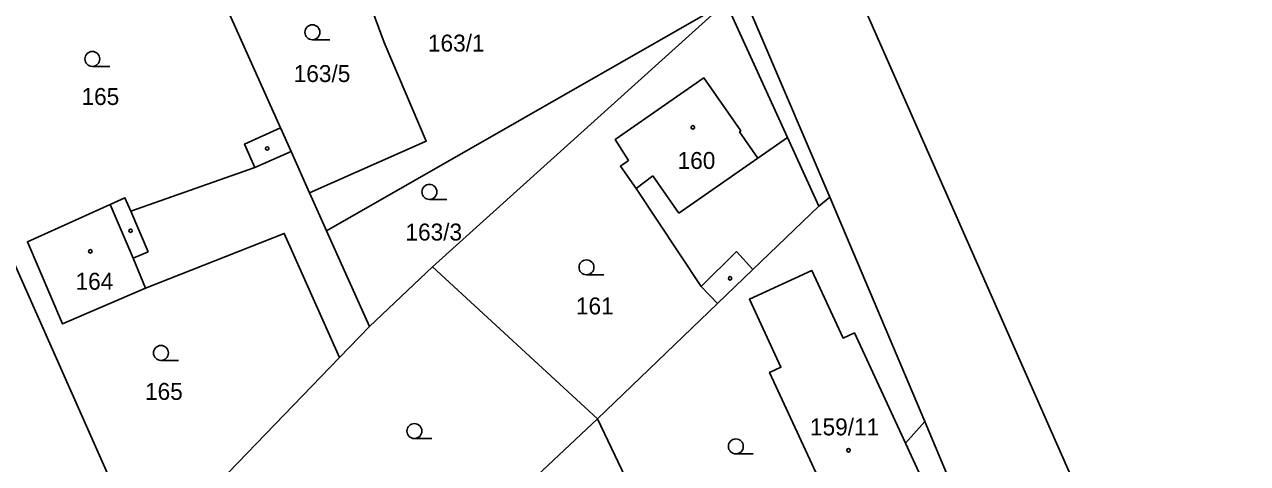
# Model space of a CAD drawing. Extents: x -724107 to -720612, y -1045267 to -1038441.
# Drawn here: x -722946.8 to -722824, y -1042363.1 to -1042319 of the extents above; entities that cross this region are included whole.
import ezdxf

# ---------------------------------------------------------------- set-up
doc = ezdxf.new("R2010")
doc.units = 0
for name, color, linetype in [('Hranice parcel', 7, 'Continuous'), ('Parcelní čísla', 7, 'Continuous'), ('Vnitřní kresba', 7, 'Continuous'), ('Značky budov', 7, 'Continuous'), ('Značky kultur', 7, 'Continuous')]:
    doc.layers.add(name, color=color, linetype=linetype)

msp = doc.modelspace()

# ---------------------------------------------------------------- linework, layer by layer
at = {"layer": 'Hranice parcel'}
for p, q in [((-722875.11, -1042288.78), (-722824.01, -1042404.46)), ((-722926.79, -1042316.73), (-722921.11, -1042329.42)), ((-722876.41, -1042316.85), (-722905.85, -1042343.37)), ((-722870.21, -1042330.38), (-722876.41, -1042316.85)), ((-722867.05, -1042337.26), (-722870.21, -1042330.38)), ((-722865.95, -1042336.37), (-722867.05, -1042337.26)), ((-722856.42, -1042358.89), (-722865.95, -1042336.37)), ((-722916.48, -1042339.75), (-722912.18, -1042349.36)), ((-722905.85, -1042343.37), (-722912.18, -1042349.36)), ((-722889.27, -1042358.62), (-722905.85, -1042343.37)), ((-722877.22, -1042347.03), (-722889.27, -1042358.62)), ((-722912.18, -1042349.36), (-722915.19, -1042352.47)), ((-722915.19, -1042352.47), (-722934.71, -1042372.64)), ((-722925.82, -1042392.75), (-722889.27, -1042358.62)), ((-722889.27, -1042358.62), (-722881.59, -1042374.72)), ((-722858.37, -1042361.05), (-722856.42, -1042358.89)), ((-722852.81, -1042367.41), (-722856.42, -1042358.89))]:
    msp.add_line(p, q, dxfattribs=at)
for points in [[(-722865.95, -1042336.37), (-722887.25, -1042286.6), (-722912.87, -1042230.53)], [(-722913.56, -1042312.92), (-722914, -1042313.18), (-722912.66, -1042316.01), (-722912.52, -1042315.95), (-722910.72, -1042320.84), (-722906.48, -1042330.75), (-722918.2, -1042335.92)], [(-722959.26, -1042316.99), (-722948.46, -1042341.61), (-722934.71, -1042372.64)], [(-722916.48, -1042339.75), (-722876.8, -1042317.07), (-722876.41, -1042316.85)], [(-722870.21, -1042330.38), (-722873.19, -1042332.46), (-722875.04, -1042329.82), (-722874.9, -1042329.73), (-722878.6, -1042324.41), (-722887.5, -1042330.6), (-722886.18, -1042332.69), (-722886.98, -1042333.25), (-722885.4, -1042335.51), (-722878.88, -1042345.33), (-722877.22, -1042347.03)], [(-722921.11, -1042329.42), (-722924.73, -1042331.04), (-722923.68, -1042333.4), (-722936.16, -1042337.78), (-722936.74, -1042336.43), (-722938.23, -1042337.1), (-722946.53, -1042340.84), (-722942.99, -1042349.09), (-722934.66, -1042345.49), (-722920.74, -1042340.01), (-722915.19, -1042352.47)], [(-722921.11, -1042329.42), (-722920.05, -1042331.78), (-722918.2, -1042335.92)], [(-722918.2, -1042335.92), (-722917.02, -1042338.54), (-722916.48, -1042339.75)], [(-722867.05, -1042337.26), (-722873.7, -1042343.64), (-722877.22, -1042347.03)], [(-722867.6, -1042371.3), (-722870.56, -1042369.01), (-722867.11, -1042364.49), (-722872, -1042353.96), (-722870.86, -1042353.43), (-722874.03, -1042346.62), (-722867.76, -1042343.73), (-722864.6, -1042350.51), (-722863.49, -1042349.99), (-722858.37, -1042361.05)], [(-722858.37, -1042361.05), (-722856.21, -1042365.7), (-722863.13, -1042374.77), (-722867.6, -1042371.3)]]:
    msp.add_lwpolyline(points, dxfattribs=at)
at = {"layer": 'Vnitřní kresba'}
for p, q in [((-722920.05, -1042331.78), (-722923.68, -1042333.4)), ((-722881.11, -1042337.99), (-722873.19, -1042332.46)), ((-722885.4, -1042335.51), (-722883.73, -1042334.23)), ((-722883.73, -1042334.23), (-722881.11, -1042337.99)), ((-722938.23, -1042337.1), (-722935.92, -1042342.49)), ((-722936.16, -1042337.78), (-722934.42, -1042341.84)), ((-722934.42, -1042341.84), (-722935.92, -1042342.49)), ((-722875.32, -1042341.81), (-722878.88, -1042345.33)), ((-722873.7, -1042343.64), (-722875.32, -1042341.81)), ((-722935.92, -1042342.49), (-722934.66, -1042345.49))]:
    msp.add_line(p, q, dxfattribs=at)
at = {"layer": 'Značky budov'}
for centre in [(-722879.71, -1042329.37), (-722922.45, -1042331.48), (-722936.17, -1042339.74), (-722940.21, -1042341.81), (-722875.97, -1042344.52), (-722864.08, -1042361.77)]:
    msp.add_circle(centre, 0.175, dxfattribs=at)
at = {"layer": 'Značky kultur'}
for p, q in [((-722917.91, -1042320.57), (-722916.16, -1042320.57)), ((-722940.01, -1042323.25), (-722938.26, -1042323.25)), ((-722906.16, -1042336.59), (-722904.41, -1042336.59)), ((-722890.39, -1042344.16), (-722888.64, -1042344.16)), ((-722933.12, -1042352.75), (-722931.37, -1042352.75)), ((-722907.67, -1042360.59), (-722905.92, -1042360.59)), ((-722875.39, -1042362.13), (-722873.64, -1042362.13))]:
    msp.add_line(p, q, dxfattribs=at)
for centre in [(-722917.91, -1042319.82), (-722940.01, -1042322.5), (-722906.16, -1042335.84), (-722890.39, -1042343.41), (-722933.12, -1042352), (-722907.67, -1042359.84), (-722875.39, -1042361.38)]:
    msp.add_circle(centre, 0.75, dxfattribs=at)

# ---------------------------------------------------------------- texts
at = {"layer": 'Parcelní čísla'}
for s, p in [('163/1', (-722906.31, -1042321.76)), ('163/5', (-722919.79, -1042324.82)), ('165', (-722941.1, -1042327.12)), ('160', (-722881.24, -1042333.54)), ('163/3', (-722908.57, -1042340.72)), ('164', (-722941.7, -1042345.66)), ('161', (-722891.45, -1042348.13)), ('165', (-722934.72, -1042356.71)), ('159/11', (-722867.95, -1042360.27))]:
    msp.add_text(s, height=1.7, dxfattribs=at).set_placement(p)

doc.saveas('drawing.dxf')
